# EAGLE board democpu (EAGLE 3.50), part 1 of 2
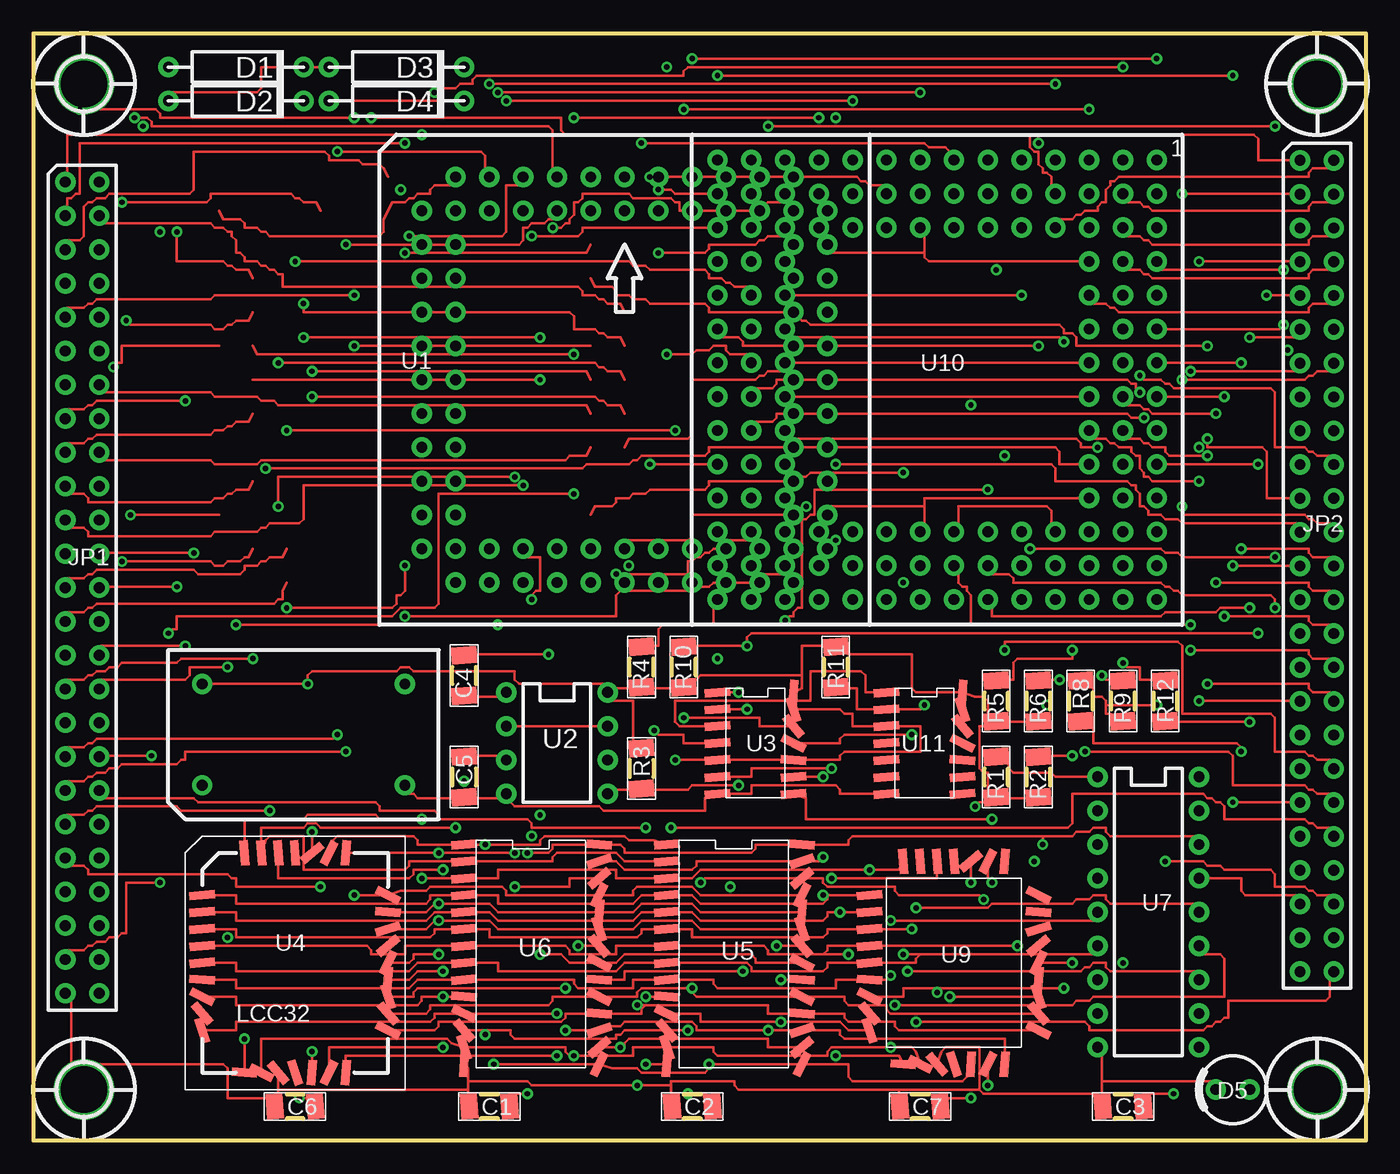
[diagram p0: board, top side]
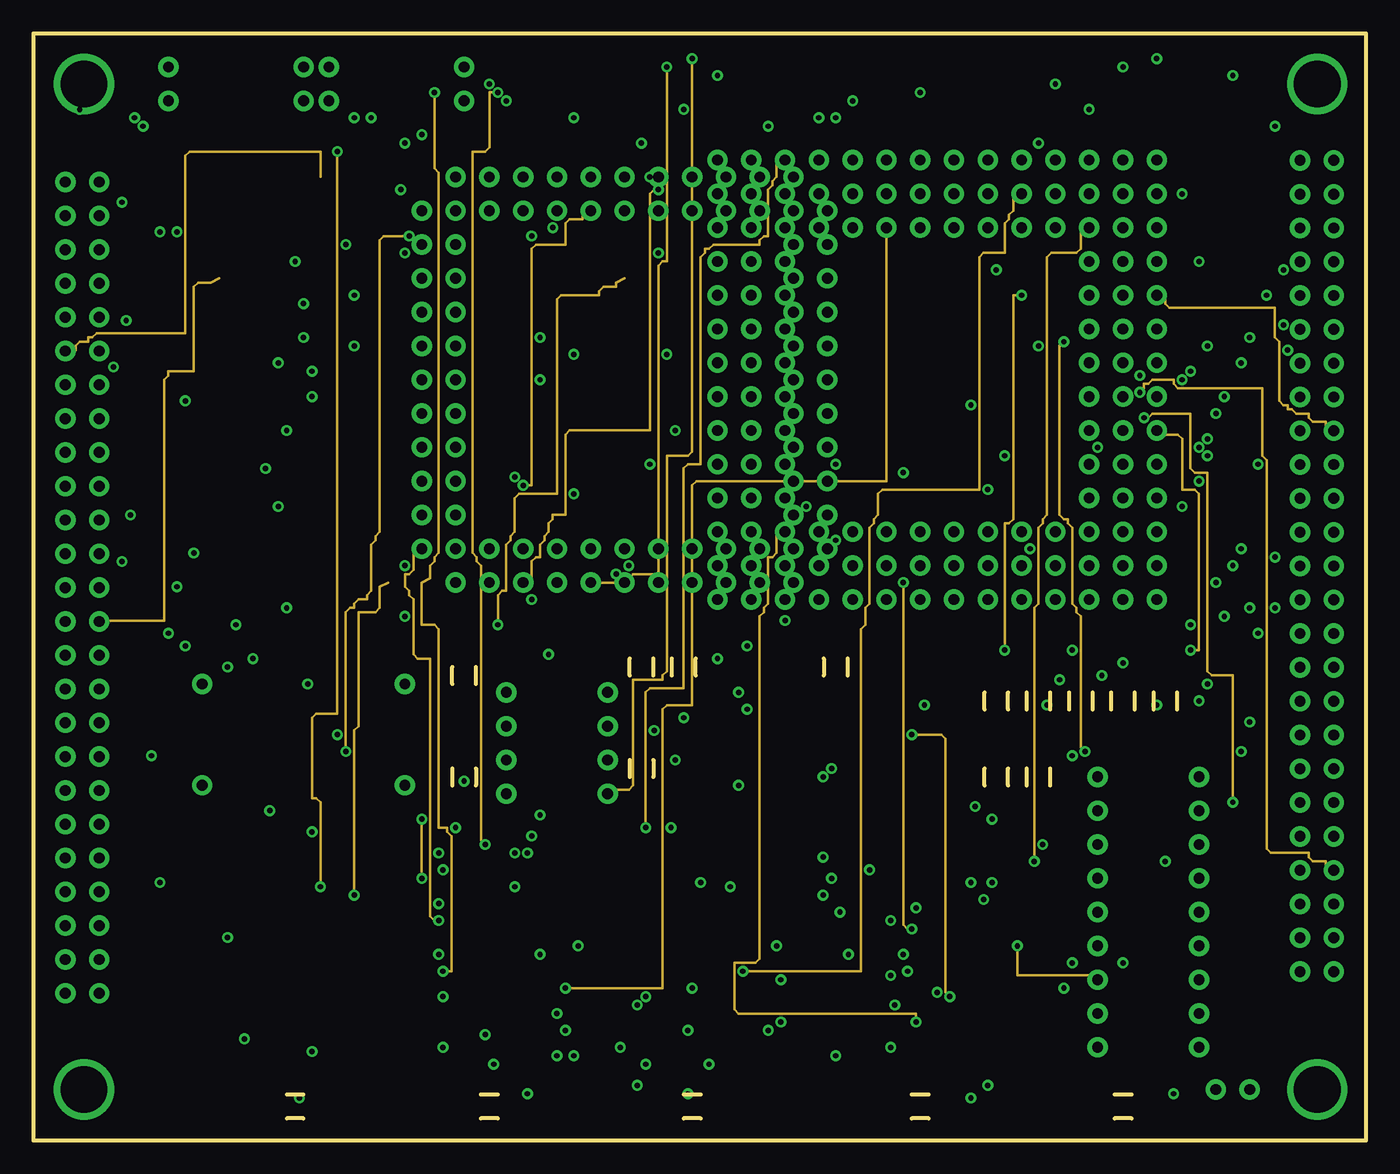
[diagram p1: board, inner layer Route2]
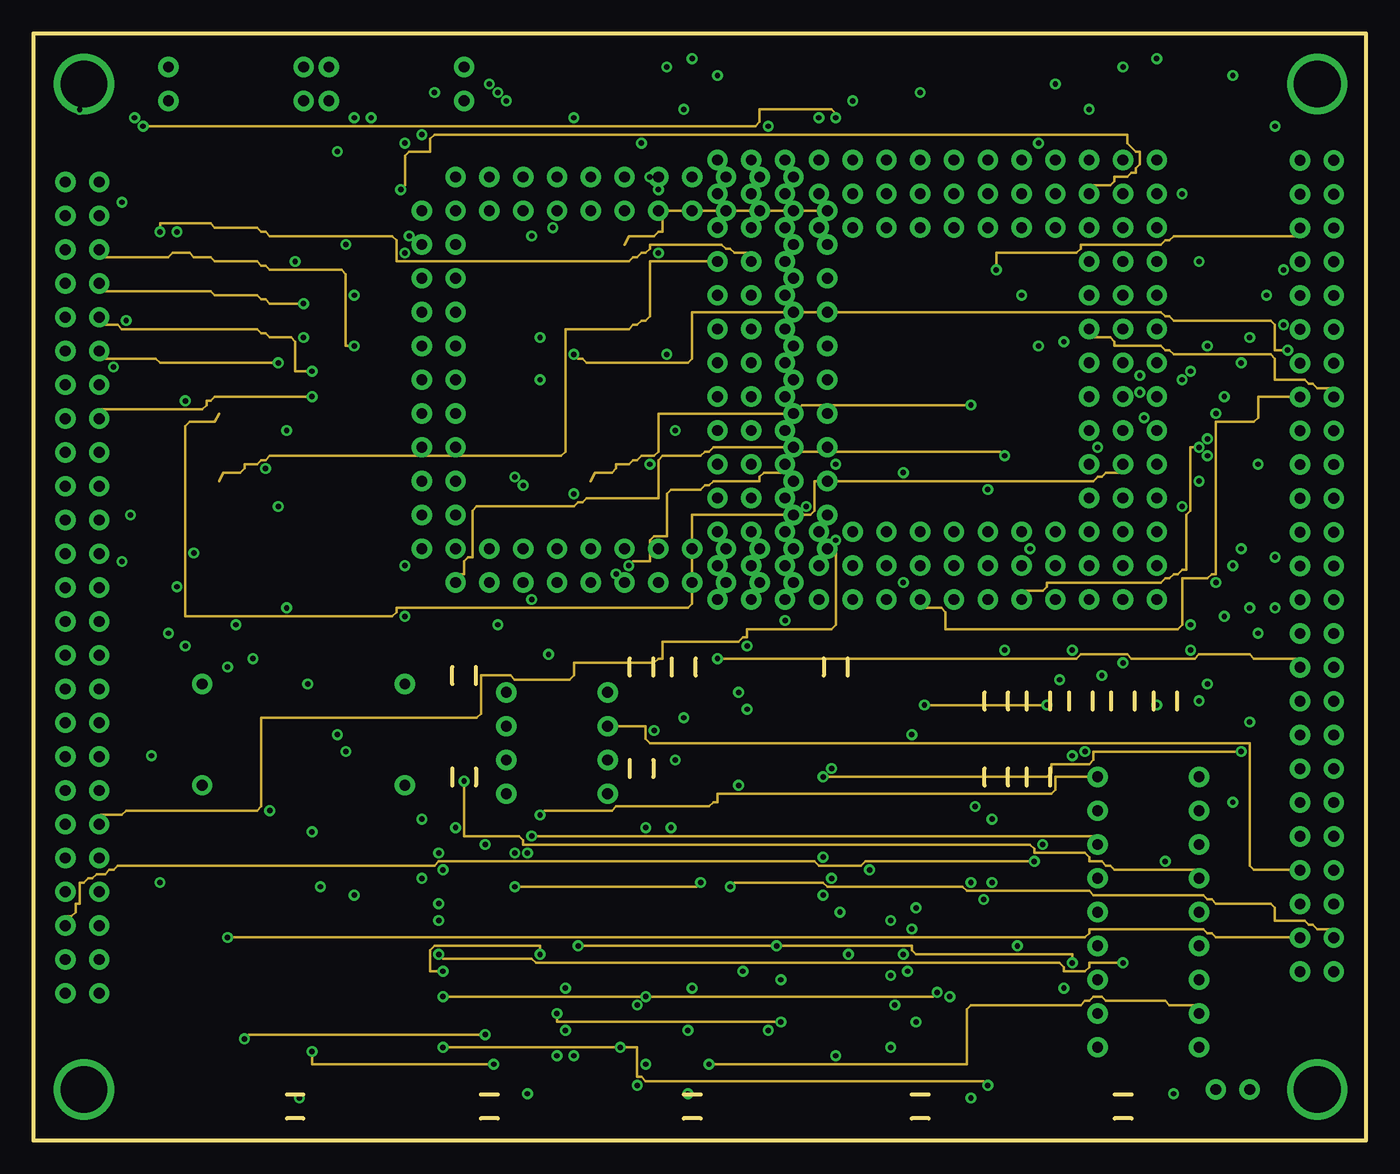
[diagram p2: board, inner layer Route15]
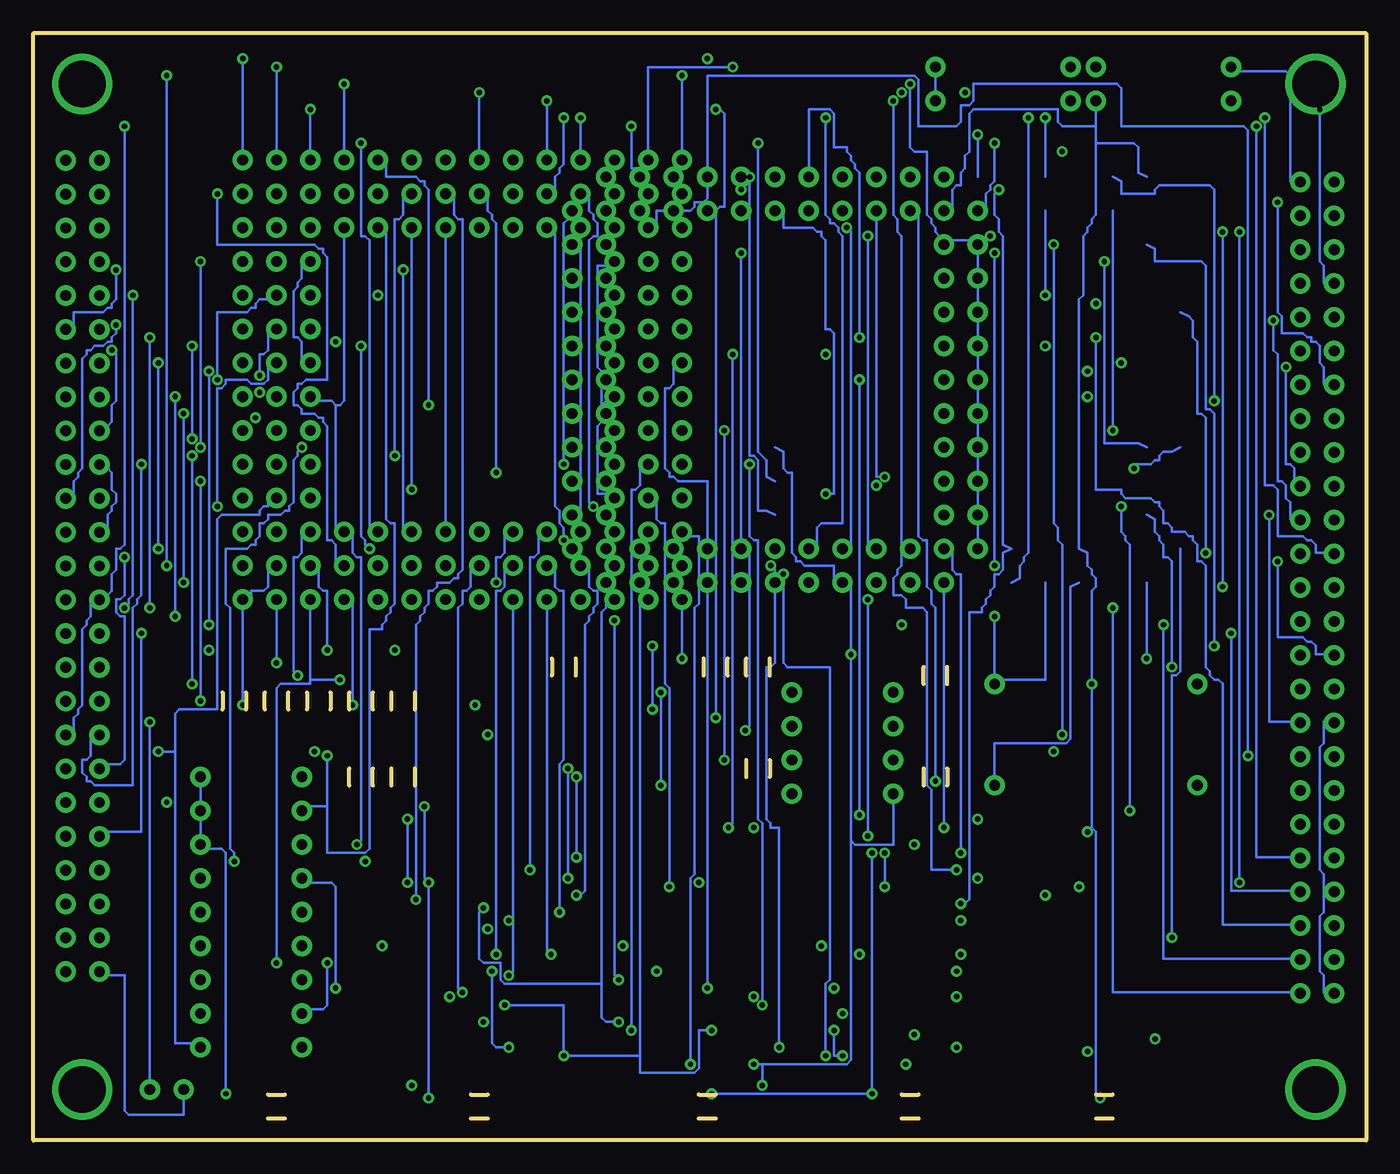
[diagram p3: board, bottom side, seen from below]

Size 100.2 x 83.19 mm. Coordinates in mm from the lower left corner, seen from the top.
Outline: 0,0 100.2,0 100.2,83.19 0,83.19 0,0
Copper layers used: Top, Route2, Route15, Bottom

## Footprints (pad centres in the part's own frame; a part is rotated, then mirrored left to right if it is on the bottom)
06 = smd 1.27 x 1.905 rotated 4.4:  1.524,0 | smd 1.27 x 1.905 rotated 4.3:  -1.524,0
4 = drill 0.813 pad 1.524 round:  0,0;  10.16,0
D = drill 0.813 pad 1.524 round:  0,0;  2.54,0
FBO3,5 = drill 3.505 pad 1.524 round:  0,0
N25X2 = drill 0.813 pad 1.524 round:  0,0;  0,2.54;  2.54,0;  2.54,2.54;  5.08,0;  5.08,2.54;  7.62,0;  7.62,2.54;  10.16,0;  10.16,2.54;  12.7,0;  15.24,0;  17.78,0;  20.32,0;  22.86,0;  25.4,0;  27.94,0;  30.48,0;  33.02,0;  35.56,0;  38.1,0;  40.64,0;  43.18,0;  45.72,0;  48.26,0;  50.8,0;  53.34,0;  55.88,0;  58.42,0;  60.96,0;  12.7,2.54;  15.24,2.54;  17.78,2.54;  20.32,2.54;  22.86,2.54;  25.4,2.54;  27.94,2.54;  30.48,2.54;  33.02,2.54;  35.56,2.54;  38.1,2.54;  40.64,2.54;  43.18,2.54;  45.72,2.54;  48.26,2.54;  50.8,2.54;  53.34,2.54;  55.88,2.54;  58.42,2.54;  60.96,2.54
CC84 = drill 0.813 pad 1.524 round:  0,-2.54;  0,-5.08;  0,-7.62;  0,-10.16;  0,-12.7;  0,-15.24;  0,-17.78;  0,-20.32;  0,-22.86;  0,-25.4;  0,-27.94;  -2.54,-30.48;  -5.08,-30.48;  -7.62,-30.48;  -10.16,-30.48;  -12.7,-30.48;  -15.24,-30.48;  -17.78,-30.48;  -20.32,-30.48;  -22.86,-30.48;  -25.4,-30.48;  -27.94,-30.48;  -30.48,-27.94;  -30.48,-25.4;  -30.48,-22.86;  -30.48,-20.32;  -30.48,-17.78;  -30.48,-15.24;  -30.48,-12.7;  -30.48,-10.16;  -30.48,-7.62;  -30.48,-5.08;  -30.48,-2.54;  -27.94,0;  -25.4,0;  -22.86,0;  -20.32,0;  -17.78,0;  -15.24,0;  -12.7,0;  -10.16,0;  -7.62,0;  -5.08,0;  -2.54,0;  -2.54,-2.54;  -2.54,-5.08;  -2.54,-7.62;  -2.54,-10.16;  -2.54,-12.7;  -2.54,-15.24;  -2.54,-17.78;  -2.54,-20.32;  -2.54,-22.86;  -2.54,-25.4;  -2.54,-27.94;  -5.08,-27.94;  -7.62,-27.94;  -10.16,-27.94;  -12.7,-27.94;  -15.24,-27.94;  -17.78,-27.94;  -20.32,-27.94;  -22.86,-27.94;  -25.4,-27.94;  -27.94,-27.94;  -27.94,-25.4;  -27.94,-22.86;  -27.94,-20.32;  -27.94,-17.78;  -27.94,-15.24;  -27.94,-12.7;  -27.94,-10.16;  -27.94,-7.62;  -27.94,-5.08;  -27.94,-2.54;  -25.4,-2.54;  -22.86,-2.54;  -20.32,-2.54;  -17.78,-2.54;  -15.24,-2.54;  -12.7,-2.54;  -10.16,-2.54;  -7.62,-2.54;  -5.08,-2.54
L8 = drill 0.813 pad 1.524 round:  0,0;  2.54,0;  5.08,0;  7.62,0;  7.62,7.62;  5.08,7.62;  2.54,7.62;  0,7.62
14 = smd 0.635 x 1.905 rotated 4.3:  0,0;  5.08,5.715 | smd 0.635 x 1.905 rotated 94.3:  0,5.715 | smd 0.635 x 1.905 rotated 4.4:  1.27,0 | smd 0.635 x 1.905 rotated 4.5:  2.54,0 | smd 0.635 x 1.905 rotated 71.8:  1.27,5.715 | smd 0.635 x 1.905 rotated 49.3:  2.54,5.715 | smd 0.635 x 1.905 rotated 4.6:  3.81,0 | smd 0.635 x 1.905 rotated 26.8:  3.81,5.715 | smd 0.635 x 1.905 rotated 4.7:  5.08,0;  6.35,0 | smd 0.635 x 1.905 rotated 5:  6.35,5.715 | smd 0.635 x 1.905 rotated 4.8:  7.62,0 | smd 0.635 x 1.905 rotated 4.9:  7.62,5.715
C32 = smd 0.635 x 1.905 rotated 4.3:  0,0 | smd 0.635 x 1.905 rotated 4.4:  -1.27,0;  3.81,-16.51 | smd 0.635 x 1.905 rotated 4.5:  -2.54,0;  3.81,0 | smd 0.635 x 1.905 rotated 4.6:  -3.81,0 | smd 0.635 x 1.905 rotated 49.5:  1.27,0 | smd 0.635 x 1.905 rotated 27:  2.54,0 | smd 0.635 x 1.905 rotated 161.8:  0,-16.51 | smd 0.635 x 1.905 rotated 139.3:  -1.27,-16.51 | smd 0.635 x 1.905 rotated 116.8:  -2.54,-16.51 | smd 0.635 x 1.905 rotated 94.3:  -3.81,-16.51 | smd 0.635 x 1.905 rotated 184.3:  1.27,-16.51 | smd 0.635 x 1.905 rotated 206.8:  2.54,-16.51 | smd 1.905 x 0.635 rotated 4.7:  -6.985,-3.175;  -6.985,-4.445 | smd 1.905 x 0.635 rotated 4.8:  -6.985,-5.715 | smd 1.905 x 0.635 rotated 4.9:  -6.985,-6.985 | smd 1.905 x 0.635 rotated 5:  -6.985,-8.255 | smd 1.905 x 0.635 rotated 4.3:  -6.985,-9.525 | smd 1.905 x 0.635 rotated 26.8:  -6.985,-10.795 | smd 1.905 x 0.635 rotated 49.3:  -6.985,-12.065 | smd 1.905 x 0.635 rotated 71.8:  -6.985,-13.335 | smd 1.905 x 0.635 rotated 206.9:  6.985,-3.175 | smd 1.905 x 0.635 rotated 184.4:  6.985,-4.445 | smd 1.905 x 0.635 rotated 161.9:  6.985,-5.715 | smd 1.905 x 0.635 rotated 139.4:  6.985,-6.985 | smd 1.905 x 0.635 rotated 116.9:  6.985,-8.255 | smd 1.905 x 0.635 rotated 94.4:  6.985,-9.525 | smd 1.905 x 0.635 rotated 71.9:  6.985,-10.795 | smd 1.905 x 0.635 rotated 49.4:  6.985,-12.065 | smd 1.905 x 0.635 rotated 26.9:  6.985,-13.335
28L = smd 0.635 x 1.905 rotated 4.3:  0,0;  11.43,0 | smd 0.635 x 1.905 rotated 4.4:  1.27,0;  10.16,10.16 | smd 0.635 x 1.905 rotated 4.5:  2.54,0 | smd 0.635 x 1.905 rotated 4.6:  3.81,0 | smd 0.635 x 1.905 rotated 4.7:  5.08,0;  6.35,0 | smd 0.635 x 1.905 rotated 4.8:  7.62,0 | smd 0.635 x 1.905 rotated 4.9:  8.89,0 | smd 0.635 x 1.905 rotated 5:  10.16,0 | smd 0.635 x 1.905 rotated 206.8:  11.43,10.16 | smd 0.635 x 1.905 rotated 184.3:  12.7,10.16 | smd 0.635 x 1.905 rotated 161.8:  13.97,10.16 | smd 0.635 x 1.905 rotated 139.3:  15.24,10.16 | smd 0.635 x 1.905 rotated 116.8:  16.51,10.16 | smd 0.635 x 1.905 rotated 94.3:  16.51,0 | smd 0.635 x 1.905 rotated 71.8:  15.24,0 | smd 0.635 x 1.905 rotated 49.3:  13.97,0 | smd 0.635 x 1.905 rotated 26.8:  12.7,0 | smd 0.635 x 1.905 rotated 26.9:  8.89,10.16 | smd 0.635 x 1.905 rotated 49.4:  7.62,10.16 | smd 0.635 x 1.905 rotated 71.9:  6.35,10.16 | smd 0.635 x 1.905 rotated 94.4:  5.08,10.16 | smd 0.635 x 1.905 rotated 116.9:  3.81,10.16 | smd 0.635 x 1.905 rotated 139.4:  2.54,10.16 | smd 0.635 x 1.905 rotated 161.9:  1.27,10.16 | smd 0.635 x 1.905 rotated 184.4:  0,10.16
L18 = drill 0.813 pad 1.524 round:  0,0;  2.54,0;  5.08,0;  7.62,0;  10.16,0;  12.7,0;  15.24,0;  17.78,0;  20.32,0;  20.32,7.62;  17.78,7.62;  15.24,7.62;  12.7,7.62;  10.16,7.62;  7.62,7.62;  5.08,7.62;  2.54,7.62;  0,7.62
Z = drill 0.813 pad 1.524 round:  0,0;  15.24,0;  15.24,7.62;  0,7.62
CC32 = smd 0.635 x 1.905 rotated 4.3:  0,0 | smd 0.635 x 1.905 rotated 4.4:  -1.27,0;  3.81,-15.24 | smd 0.635 x 1.905 rotated 4.5:  -2.54,0;  3.81,0 | smd 0.635 x 1.905 rotated 4.6:  -3.81,0 | smd 1.905 x 0.635 rotated 4.7:  -6.35,-2.54;  -6.35,-3.81 | smd 1.905 x 0.635 rotated 71.9:  6.35,-10.16 | smd 1.905 x 0.635 rotated 49.4:  6.35,-11.43 | smd 1.905 x 0.635 rotated 26.9:  6.35,-12.7 | smd 0.635 x 1.905 rotated 206.8:  2.54,-15.24 | smd 1.905 x 0.635 rotated 94.4:  6.35,-8.89 | smd 1.905 x 0.635 rotated 116.9:  6.35,-7.62 | smd 1.905 x 0.635 rotated 139.4:  6.35,-6.35 | smd 1.905 x 0.635 rotated 161.9:  6.35,-5.08 | smd 1.905 x 0.635 rotated 184.4:  6.35,-3.81 | smd 0.635 x 1.905 rotated 184.3:  1.27,-15.24 | smd 1.905 x 0.635 rotated 4.8:  -6.35,-5.08 | smd 1.905 x 0.635 rotated 4.9:  -6.35,-6.35 | smd 1.905 x 0.635 rotated 5:  -6.35,-7.62 | smd 1.905 x 0.635 rotated 4.3:  -6.35,-8.89 | smd 1.905 x 0.635 rotated 26.8:  -6.35,-10.16 | smd 1.905 x 0.635 rotated 49.3:  -6.35,-11.43 | smd 1.905 x 0.635 rotated 71.8:  -6.35,-12.7 | smd 0.635 x 1.905 rotated 94.3:  -3.81,-15.24 | smd 0.635 x 1.905 rotated 116.8:  -2.54,-15.24 | smd 0.635 x 1.905 rotated 139.3:  -1.27,-15.24 | smd 0.635 x 1.905 rotated 161.8:  0,-15.24 | smd 0.635 x 1.905 rotated 49.5:  1.27,0 | smd 0.635 x 1.905 rotated 27:  2.54,0 | smd 1.905 x 0.635 rotated 206.9:  6.35,-2.54
A132 = drill 0.813 pad 1.524 round:  0,0;  0,-2.54;  0,-5.08;  0,-7.62;  0,-10.16;  0,-12.7;  0,-15.24;  0,-17.78;  0,-20.32;  0,-22.86;  0,-25.4;  0,-27.94;  0,-30.48;  0,-33.02;  -2.54,0;  -2.54,-2.54;  -2.54,-5.08;  -2.54,-7.62;  -2.54,-10.16;  -2.54,-12.7;  -2.54,-15.24;  -2.54,-17.78;  -2.54,-20.32;  -2.54,-22.86;  -2.54,-25.4;  -2.54,-27.94;  -2.54,-30.48;  -2.54,-33.02;  -5.08,0;  -5.08,-2.54;  -5.08,-5.08;  -5.08,-7.62;  -5.08,-10.16;  -5.08,-12.7;  -5.08,-15.24;  -5.08,-17.78;  -5.08,-20.32;  -5.08,-22.86;  -5.08,-25.4;  -5.08,-27.94;  -5.08,-30.48;  -5.08,-33.02;  -7.62,0;  -7.62,-2.54;  -7.62,-5.08;  -7.62,-27.94;  -7.62,-30.48;  -7.62,-33.02;  -10.16,0;  -10.16,-2.54;  -10.16,-5.08;  -10.16,-27.94;  -10.16,-30.48;  -10.16,-33.02;  -12.7,0;  -12.7,-2.54;  -12.7,-5.08;  -12.7,-27.94;  -12.7,-30.48;  -12.7,-33.02;  -15.24,0;  -15.24,-2.54;  -15.24,-5.08;  -15.24,-27.94;  -15.24,-30.48;  -15.24,-33.02;  -17.78,0;  -17.78,-2.54;  -17.78,-5.08;  -17.78,-27.94;  -17.78,-30.48;  -17.78,-33.02;  -20.32,0;  -20.32,-2.54;  -20.32,-5.08;  -20.32,-27.94;  -20.32,-30.48;  -20.32,-33.02;  -22.86,0;  -22.86,-2.54;  -22.86,-5.08;  -22.86,-27.94;  -22.86,-30.48;  -22.86,-33.02;  -25.4,0;  -25.4,-2.54;  -25.4,-5.08;  -25.4,-27.94;  -25.4,-30.48;  -25.4,-33.02;  -27.94,0;  -27.94,-2.54;  -27.94,-5.08;  -27.94,-7.62;  -27.94,-10.16;  -27.94,-12.7;  -27.94,-15.24;  -27.94,-17.78;  -27.94,-20.32;  -27.94,-22.86;  -27.94,-25.4;  -27.94,-27.94;  -27.94,-30.48;  -27.94,-33.02;  -30.48,0;  -30.48,-2.54;  -30.48,-5.08;  -30.48,-7.62;  -30.48,-10.16;  -30.48,-12.7;  -30.48,-15.24;  -30.48,-17.78;  -30.48,-20.32;  -30.48,-22.86;  -30.48,-25.4;  -30.48,-27.94;  -30.48,-30.48;  -30.48,-33.02;  -33.02,0;  -33.02,-2.54;  -33.02,-5.08;  -33.02,-7.62;  -33.02,-10.16;  -33.02,-12.7;  -33.02,-15.24;  -33.02,-17.78;  -33.02,-20.32;  -33.02,-22.86;  -33.02,-25.4;  -33.02,-27.94;  -33.02,-30.48;  -33.02,-33.02

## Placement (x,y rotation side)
C1  [06]  34.29,2.54 180 top
C2  [06]  49.53,2.54 180 top
C3  [06]  81.92,2.54 180 top
C4  [06]  32.38,34.92 90 top
C5  [06]  32.38,27.3 270 top
C6  [06]  19.68,2.54 180 top
C7  [06]  66.67,2.54 180 top
D1  [4]  20.32,80.65 180 top
D2  [4]  20.32,78.1 180 top
D3  [4]  32.38,80.65 180 top
D4  [4]  32.38,78.1 180 top
D5  [D]  88.9,3.81 0 top
E$38  [FBO3,5]  3.81,79.38 90 top
E$39  [FBO3,5]  3.81,3.81 0 top
E$40  [FBO3,5]  96.52,3.81 0 top
E$41  [FBO3,5]  96.52,79.38 180 top
JP1  [N25X2]  2.41,72.01 270 top
JP2  [N25X2]  95.22,73.63 270 top
R1  [06]  72.39,27.3 90 top
R2  [06]  75.56,27.3 90 top
R3  [06]  45.72,27.94 270 top
R4  [06]  45.72,35.56 90 top
R5  [06]  72.39,33.02 90 top
R6  [06]  75.56,33.02 90 top
R8  [06]  78.74,33.02 270 top
R9  [06]  81.92,33.02 90 top
R10  [06]  48.9,35.56 90 top
R11  [06]  60.33,35.56 270 top
R12  [06]  85.09,33.02 270 top
U1  [CC84]  29.21,72.39 90 top
U2  [L8]  35.56,33.66 270 top
U3  [14]  51.44,33.66 270 top
U4  [C32]  19.68,21.59 0 top
U5  [28L]  47.62,22.23 270 top
U6  [28L]  32.38,22.23 270 top
U7  [L18]  80.01,27.3 270 top
U8  [Z]  12.7,26.67 0 top
U9  [CC32]  69.22,20.96 0 top
U10  [A132]  84.45,73.66 0 top
U11  [14]  64.14,33.66 270 top

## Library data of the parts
C1-C7 R1-R6 R8-R12 U3-U6 U9 U11 = SMDPACK
D1-D5 = SEMICON
E$38-E$41 U1 U2 U7 U8 U10 = PACKAGES
JP1 JP2 = CONNEC

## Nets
A0-1: JP2. U10.
A1-1: JP2. U10.
A2-1: JP2. U10.
A3-1: JP2. U10.
A4-1: JP2. U10.
A5-1: JP2. U10.
A6-1: JP2. U10.
A7-1: JP2. U10.
A8-1: JP2. U10.
A9-1: JP2. U10.
A10-1: JP2. U10.
A11-1: JP2. U10.
A12-1: JP2. U10.
A13-1: JP2. U10.
A14-1: JP2. U10.
A15-1: JP2. U10.
ALE-1: JP2. U10.
ALEM-1: U1. U7. U10.
AM0-1: U4. U5. U6. U7. U9. U10.
AM1-1: U4. U5. U6. U7. U9. U10.
AM2-1: U4. U5. U6. U7. U9. U10.
AM3-1: U4. U5. U6. U7. U9. U10.
AM4-1: U4. U5. U6. U9. U10.
AM5-1: U4. U5. U6. U9. U10.
AM6-1: U4. U5. U6. U9. U10.
AM7-1: U4. U5. U6. U9. U10.
B0-1: JP1. U1.
B1-1: JP1. U1.
BC1-1: JP1. U1.
BDIR-1: JP1. U1.
CCLK-1: JP2. U10.
CLK-1: U1. U8. U10.
CS0-1: JP1. U10.
CS1-1: JP1. U10.
CS2-1: JP1. U10.
CS3-1: JP1. U10.
CS4-1: U4. U10.
CS5-1: U5. U10.
CS6-1: U6. U10.
CS7-1: R2. U7. U10.
CS8-1: U3. U10.
CS9-1: U3. U10.
D1-1: JP2. U10.
D2-1: JP2. U10.
D3-1: JP2. U10.
D4-1: JP2. U10.
D5-1: JP2. U10.
D6-1: JP2. U10.
D7-1: JP2. U10.
DIN-1: JP2. U10.
DM0-1: U4. U5. U6. U7. U9. U10.
DM1-1: U4. U5. U6. U7. U9. U10.
DM2-1: U4. U5. U6. U7. U9. U10.
DM3-1: U4. U5. U6. U7. U9. U10.
DM4-1: U4. U5. U6. U9. U10.
DM5-1: U4. U5. U6. U9. U10.
DM6-1: U4. U5. U6. U9. U10.
DM7-1: U4. U5. U6. U9. U10.
DP0-1: JP2. U10.
DP1-1: JP2. U10.
DP2-1: JP2. U10.
DP3-1: JP2. U10.
DP4-1: JP2. U10.
DP5-1: JP2. U10.
DP6-1: JP2. U10.
DP7-1: JP2. U10.
EP0-1: U1. U10.
EP1-1: U1. U10.
GND: C1. C2. C3. C4. C5. C6. C7. D5. JP1. JP2. U1. U2. U3. U4. U5. U6. U7. U8. U9. U10. U11.
HDC-1: R12. U10.
LDC-1: R11. U10. U11.
N00044: R5. U10.
N00107: D1. D2. D3.
N00117: C5. U2.
N00118: C4. U2.
N00119: U3. U9.
N00121: U3. U9.
N00124: U3. U9.
N00135: U3. U11.
N00157: D5. R12.
P00-1: U1. U10.
P01-1: U1. U10.
P02-1: U1. U10.
P03-1: U1. U10.
P04-1: U1. U10.
P05-1: U1. U10.
P06-1: U1. U10.
P07-1: U1. U10.
P10-1: JP1. U1.
P11-1: JP1. U1.
P12-1: JP1. U1.
P13-1: JP1. U1.
P14-1: JP2. U1.
P15-1: JP1. U1.
P16-1: JP1. U1.
P20-1: U1. U4. U5. U6. U10.
P21-1: U1. U4. U5. U6. U10.
P22-1: U1. U4. U5. U6. U10.
P23-1: U1. U4. U5. U6. U10.
P24-1: U1. U4. U5. U6. U10.
P25-1: U1. U4. U5. U6. U10.
P26-1: U1. U4. U5. U6. U10.
P27-1: U1. U4. U10.
P40-1: JP1. U1.
P41-1: JP1. U1.
P42-1: JP1. U1.
P43-1: JP1. U1.
P44-1: JP1. U1.
P45-1: JP1. U1.
P46-1: JP1. U1.
P47-1: JP1. U1.
P50-1: JP1. U1.
P51-1: JP1. U1.
P52-1: JP1. U1.
P53-1: JP1. U1.
P54-1: JP1. U1.
P55-1: JP1. U1.
P56-1: JP1. U1.
P57-1: JP1. U1.
P66-1: JP1. U1.
P67-1: JP1. U1.
P70-1: JP1. U1.
P71-1: JP1. U1.
P72-1: JP1. U1.
P73-1: JP1. U1.
P74-1: JP1. U1.
P75-1: JP1. U1.
P80-1: JP1. U1.
P81-1: JP1. U1.
P82-1: JP1. U1.
P83-1: JP1. U1.
PDWN-1: R3. U2. U3. U10.
PSEN-1: JP2. U10.
PSENM-1: U1. U10.
RD-1: JP2. U10.
RDM-1: U5. U6. U7. U9.
RDP-1: U1. U10.
RDR-1: JP1. U10.
RDRM-1: R6. U4. U10.
RES-1: U1. U3. U11.
RLCA-1: JP2. R4. U10.
RSI-1: JP2. R10. U3.
RSO-1: JP2. U1. U7.
RX0-1: JP2. U1.
RX1-1: JP2. U1.
S$1: D3. D4.
S$2: U1.
S$3: R8. R9. U10.
SENS-1: JP2. U2.
STD-1: R1. U1. U7.
T0-1: JP1. U1.
T2-1: JP1. U1.
TX1-1: JP2. U1.
VB: C1. C2. C3. JP2. U5. U6. U7. U10.
VCC: C6. C7. D2. R1. R2. R3. R4. R5. R6. R10. R11. U1. U2. U3. U4. U8. U9. U11.
VM: D1. JP1.
WR-1: JP2. U10.
WRM-1: R8. U3. U5. U6. U7. U10.
WRP-1: U1. U10.
WRR-1: JP1. U10.
WRRM-1: R9. U10.

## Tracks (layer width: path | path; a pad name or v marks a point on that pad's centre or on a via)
A0-1
  Top 0.203: 97.77,71.09 97.47,70.49 96.2,70.49 95.89,70.17 95.89,69.85 84.14,69.85 83.82,70.17 83.5,70.17 83.19,70.49 82.23,70.49 81.92,71.12
A1-1
  Top 0.203: 97.77,68.56 97.47,67.94 96.2,67.94 95.89,67.63 95.89,67.31 84.14,67.31 83.82,67.63 83.5,67.63 83.19,67.94 82.23,67.94 81.92,68.58
A2-1
  Top 0.203: 97.77,66.02 97.47,65.41 96.2,65.41 95.89,65.09 95.89,64.77 84.14,64.77 83.82,65.09 83.5,65.09 83.19,65.41 82.23,65.41 81.92,66.04
A3-1
  Top 0.203: 97.77,63.48 97.47,62.87 96.2,62.87 95.89,62.55 95.89,62.23 81.6,62.23 81.28,62.55 80.96,62.55 80.64,62.87 79.69,62.87 79.38,63.5
A4-1  (via drill 0.41 pad 0.61)
  Top 0.203: v93.98,65.41 84.77,65.41 84.45,66.04
  Bottom 0.203: v93.98,65.41 93.98,63.18 94.3,62.87 94.3,62.55 94.61,62.55 94.93,62.23 97.16,62.23 97.16,61.28 97.77,60.94
A5-1  (via drill 0.41 pad 0.61)
  Top 0.203: v86.36,57.15 95.57,57.15 95.89,57.47 96.2,57.47 96.52,57.79 97.47,57.79 97.77,58.4
  Bottom 0.203: v86.36,57.15 86.36,62.23 84.14,62.23 83.82,62.55 83.5,62.55 83.5,62.87 83.19,63.18 82.55,63.18 81.92,63.5
A6-1
  Route15 0.203: 79.38,60.96 79.69,60.33 80.96,60.33 81.28,60.01 81.28,59.69 84.77,59.69 85.09,59.37 85.41,59.37 85.72,59.05 93.03,59.05 93.34,58.74 93.34,57.15 95.57,57.15 95.89,56.83 96.2,56.83 96.52,56.52 97.47,56.52 97.77,55.85
A7-1
  Route2 0.203: 84.45,63.5 85.09,63.18 85.09,62.87 85.41,62.55 93.34,62.55 93.34,60.33 93.66,60.01 93.66,55.56 93.98,55.24 94.3,55.24 94.3,54.93 94.61,54.93 94.93,54.61 95.89,54.61 95.89,54.29 96.2,53.98 97.16,53.98 97.16,53.66 97.77,53.31
A8-1  (via drill 0.41 pad 0.61)
  Top 0.203: v83.19,57.47 83.5,57.15 84.77,57.15 85.09,56.83 85.41,56.83 85.72,56.52 93.03,56.52 93.34,56.2 93.34,52.07 95.57,52.07 95.89,51.75 96.2,51.75 96.52,51.44 97.47,51.44 97.77,50.77
  Bottom 0.203: v83.19,57.47 83.19,59.05 82.87,59.05 82.55,59.37 82.55,60.64 81.92,60.96
A9-1  (via drill 0.41 pad 0.61)
  Top 0.203: v93.98,61.28 93.66,60.96 84.45,60.96
  Bottom 0.203: v93.98,61.28 93.98,60.64 94.3,60.33 94.3,60.01 94.61,60.01 94.93,59.69 95.57,59.69 95.89,59.37 96.2,59.37 96.2,59.05 96.52,58.74 96.52,50.48 96.84,50.16 96.84,49.85 97.16,49.53 97.16,48.58 97.77,48.23
A10-1  (via drill 0.41 pad 0.61)
  Top 0.203: v86.36,47.62 86.36,46.99 95.57,46.99 95.89,46.67 96.2,46.67 96.52,46.35 97.47,46.35 97.77,45.7
  Bottom 0.203: v86.36,47.62 86.36,56.52 86.04,56.52 85.72,56.83 85.72,57.15 84.14,57.15 83.82,56.83 82.87,56.83 82.55,57.15 82.55,58.1 81.92,58.42
A11-1  (via drill 0.41 pad 0.61)
  Top 0.203: v90.81,44.45 95.89,44.45 95.89,44.13 96.2,43.81 97.47,43.81 97.77,43.16 | v90.81,58.42 84.45,58.42
  Bottom 0.203: v90.81,44.45 v90.81,58.42
A12-1  (via drill 0.41 pad 0.61)
  Top 0.203: v88.9,41.91 95.89,41.91 95.89,41.59 96.2,41.27 97.47,41.27 97.77,40.62 | v88.9,54.61 84.14,54.61 83.82,54.93 83.5,54.93 83.19,55.24 82.23,55.24 81.92,55.88
  Bottom 0.203: v88.9,41.91 v88.9,54.61
A13-1  (via drill 0.41 pad 0.61)
  Top 0.203: v89.53,39.37 95.89,39.37 95.89,39.05 96.2,38.73 97.47,38.73 97.77,38.08 | v89.53,55.88 84.45,55.88
  Bottom 0.203: v89.53,39.37 v89.53,55.88
A14-1  (via drill 0.41 pad 0.61)
  Top 0.203: v87,36.83 95.89,36.83 95.89,36.51 96.2,36.2 97.47,36.2 97.77,35.53
  Route2 0.203: v87,36.83 87.63,36.83 87.63,48.58 87.31,48.9 86.36,48.9 86.36,52.7 86.04,53.02 85.09,53.02 84.45,53.34
A15-1  (via drill 0.41 pad 0.61)
  Top 0.203: v88.27,34.29 95.89,34.29 95.89,33.97 96.2,33.66 97.47,33.66 97.77,33 | v88.27,51.44 85.41,51.44 85.09,51.75 85.09,52.07 84.14,52.07 83.82,52.39 83.5,52.39 83.19,52.7 82.23,52.7 81.92,53.34
  Bottom 0.203: v88.27,34.29 v88.27,51.44
ALE-1  (via drill 0.41 pad 0.61)
  Top 0.203: v87.63,33.02 94.61,33.02 95.22,33 | v87.63,49.53 84.14,49.53 83.82,49.85 83.5,49.85 83.5,50.16 83.19,50.48 83.19,51.44 82.87,51.44 82.55,51.75 82.55,52.07 81.6,52.07 81.28,52.39 80.96,52.39 80.64,52.7 79.69,52.7 79.38,53.34
  Bottom 0.203: v87.63,33.02 v87.63,49.53
ALEM-1  (via drill 0.41 pad 0.61)
  Top 0.203: v37.47,67.94 40.96,67.94 41.27,68.26 41.27,68.58 51.44,68.58 | v37.47,40.64 37.47,40.96 37.78,41.27 38.1,41.27 38.1,43.81 37.15,43.81 36.83,44.45
  Route15 0.203: v37.47,22.86 79.69,22.86 80.01,22.23
  Bottom 0.203: v37.47,67.94 37.47,44.77 36.83,44.45 | v37.47,22.86 v37.47,40.64
AM0-1  (via drill 0.41 pad 0.61)
  Top 0.203: 12.7,10.79 15.24,10.79 15.24,10.16 28.89,10.16 29.21,10.48 29.21,10.79 v30.8,10.79 32.38,10.79 | v46.04,10.79 47.62,10.79 | 67.94,11.43 v77.47,11.43 | 67.94,11.43 65.41,11.43 65.41,10.79 62.87,10.79 | v67.94,11.11 67.94,11.43
  Route15 0.203: v30.8,10.79 v46.04,10.79 67.63,10.79 v67.94,11.11
  Bottom 0.203: v77.47,11.43 77.47,19.05 77.79,19.37 79.38,19.37 80.01,19.69 | v67.94,11.11 68.26,11.43 68.26,40.01 67.94,40.32 67.94,41.27 67.63,41.27 67.31,41.59 67.31,42.86 66.67,43.18
AM1-1  (via drill 0.41 pad 0.61)
  Top 0.203: 12.7,12.07 15.24,12.07 15.24,11.43 28.26,11.43 28.89,12.07 32.38,12.07 40.64,12.07 40.64,11.75 40.96,11.43 45.09,11.43 45.09,12.07 47.62,12.07 51.12,12.07 51.12,11.75 51.44,11.43 60.33,11.43 60.33,12.07 62.87,12.07 64.14,12.07 v64.45,12.38 | v64.45,16.51 79.69,16.51 80.01,17.14
  Bottom 0.203: 64.14,16.51 64.14,12.7 v64.45,12.38 | 64.14,16.51 64.14,40.64 | 64.14,16.51 v64.45,16.51
AM2-1  (via drill 0.41 pad 0.61)
  Top 0.203: 12.7,13.34 15.24,13.34 15.24,12.7 28.26,12.7 28.89,13.34 32.38,13.34 34.92,13.34 34.92,12.7 43.81,12.7 44.45,13.34 47.62,13.34 53.66,13.34 53.98,13.02 53.98,12.7 59.37,12.7 59.69,13.02 59.69,13.34 62.87,13.34 66.36,13.34 66.36,13.65 66.67,13.97 | 66.67,13.97 79.69,13.97 80.01,14.61 | 66.67,13.97 v65.41,13.97
  Bottom 0.203: v65.41,13.97 65.41,41.27 65.09,41.27 64.77,41.59 64.77,42.86 64.14,43.18
AM3-1  (via drill 0.41 pad 0.61)
  Top 0.203: 12.7,14.61 25.08,14.61 25.4,14.29 25.4,13.97 27.94,13.97 27.94,14.61 32.38,14.61 40.01,14.61 40.32,14.29 40.32,13.97 43.81,13.97 43.81,14.61 47.62,14.61 54.93,14.61 55.24,14.29 55.24,13.97 59.37,13.97 | 59.37,13.97 59.69,14.29 59.69,14.61 62.87,14.61 v73.98,14.61 | 59.37,13.97 v61.28,13.97
  Route2 0.203: v73.98,14.61 73.98,12.38 79.38,12.38 80.01,12.07
  Bottom 0.203: v61.28,13.97 61.59,14.29 61.59,40.64
AM4-1  (via drill 0.41 pad 0.61)
  Top 0.203: 12.7,15.88 15.24,15.88 15.24,15.24 29.84,15.24 30.16,15.56 30.16,15.88 32.38,15.88 34.29,15.88 34.29,15.24 45.4,15.24 45.72,15.56 45.72,15.88 47.62,15.88 49.53,15.88 49.53,15.24 59.37,15.24 59.69,15.56 59.69,15.88 62.87,15.88 v66.04,15.88
  Route2 0.203: v65.41,41.91 65.41,16.19 65.72,15.88 v66.04,15.88
  Bottom 0.203: v65.41,41.91 65.41,43.81 65.09,43.81 64.77,44.13 64.77,45.4 64.14,45.72
AM5-1  (via drill 0.41 pad 0.61)
  Top 0.203: 12.7,17.14 15.24,17.14 15.24,16.51 29.53,16.51 30.16,17.14 32.38,17.14 34.29,17.14 34.92,16.51 45.09,16.51 45.72,17.14 47.62,17.14 49.53,17.14 50.16,16.51 59.37,16.51 59.69,16.83 59.69,17.14 v60.64,17.14 62.87,17.14
  Bottom 0.203: v60.64,17.14 60.64,28.26 60.33,28.57 60.33,41.27 60.64,41.27 60.96,41.59 60.96,42.86 61.59,43.18
AM6-1  (via drill 0.41 pad 0.61)
  Top 0.203: 12.7,18.41 15.24,18.41 15.24,17.78 29.53,17.78 29.84,18.1 29.84,18.41 32.38,18.41 34.92,18.41 34.92,17.78 45.09,17.78 45.72,18.41 47.62,18.41 49.53,18.41 50.16,17.78 59.37,17.78 59.69,18.1 59.69,18.41 | 59.69,18.41 62.87,18.41 | 59.69,18.41 v59.37,18.41
  Bottom 0.203: v59.37,18.41 59.05,18.41 58.74,18.73 58.74,38.73 58.42,39.05 58.42,39.37 58.1,39.69 58.1,40.01 57.78,40.32 57.78,41.27 58.1,41.27 58.42,41.59 58.42,42.86 59.05,43.18
AM7-1  (via drill 0.41 pad 0.61)
  Top 0.203: v29.21,24.13 26.04,24.13 25.72,24.45 20.64,24.45 20.32,24.13 15.88,24.13 15.88,21.59 | v29.21,19.69 32.38,19.69 34.92,19.69 34.92,20.32 43.81,20.32 43.81,19.69 47.62,19.69 49.53,19.69 50.16,20.32 v62.87,20.32 65.09,20.32 65.41,20.96
  Route2 0.203: v29.21,24.13 v29.21,19.69
  Bottom 0.203: v62.87,20.32 62.87,43.81 62.55,43.81 62.23,44.13 62.23,45.4 61.59,45.72
B0-1  (via drill 0.41 pad 0.61)
  Top 0.203: v10.16,38.1 10.48,38.42 10.79,38.42 10.79,39.37 26.99,39.37 27.62,40.01 30.16,40.01 30.48,40.32 30.48,48.58 v40.64,48.58
  Bottom 0.203: v10.16,38.1 10.16,18.73 5.71,18.73 4.95,18.67 | v40.64,48.58 40.01,48.58 40.01,60.64 40.32,60.96 40.64,60.96 40.64,67.63 40.96,67.94 40.96,68.26 41.27,68.26 41.59,68.58 43.81,68.58 43.81,69.53 44.45,69.85
B1-1  (via drill 0.41 pad 0.61)
  Top 0.203: v20.32,60.33 v38.1,60.33
  Bottom 0.203: v20.32,60.33 20.32,48.9 18.41,48.9 18.41,48.58 18.1,48.26 16.19,48.26 15.88,47.94 15.56,47.94 15.56,47.62 15.24,47.31 15.24,46.35 14.92,46.35 14.61,46.04 14.61,45.72 13.65,45.72 13.34,45.4 13.02,45.4 13.02,45.09 12.7,44.77 12.7,43.5 12.38,43.5 12.06,43.18 12.06,35.56 11.75,35.24 11.75,34.92 11.43,34.61 11.11,34.61 10.79,34.29 10.79,16.19 5.71,16.19 4.95,16.13 | v38.1,60.33 38.1,72.71 38.42,73.03 38.42,73.34 38.73,73.66 38.73,73.98 39.05,74.29 39.05,74.61 40.01,74.61 40.01,77.15 40.32,77.47 41.91,77.47 41.91,72.39
BC1-1  (via drill 0.41 pad 0.61)
  Top 0.203: v19.05,40.01 26.99,40.01 27.3,40.32 27.3,40.96 27.62,40.96 27.94,41.27 v27.94,43.18 | v27.94,66.67 41.59,66.67 41.91,67.31
  Bottom 0.203: v19.05,40.01 19.05,11.11 5.71,11.11 JP1. | v27.94,43.18 v27.94,66.67
BDIR-1  (via drill 0.41 pad 0.61)
  Top 0.203: v15.24,38.73 v34.92,38.73
  Route2 0.203: v34.92,38.73 34.92,40.96 35.24,41.27 35.56,41.27 35.56,44.77 35.88,45.09 35.88,45.4 36.2,45.72 36.2,48.26 36.51,48.58 39.37,48.58 39.37,63.18 39.69,63.5 42.55,63.5 42.55,63.82 42.86,64.13 43.81,64.13 43.81,64.45 44.45,64.77
  Bottom 0.203: v15.24,38.73 15.24,13.65 5.71,13.65 4.95,13.59
CCLK-1  (via drill 0.41 pad 0.61)
  Top 0.203: v51.44,80.01 v90.17,80.01 | v90.17,43.18 94.61,43.18 95.22,43.16
  Bottom 0.203: v90.17,80.01 v90.17,43.18 | 51.44,73.66 v51.44,80.01
CLK-1  (via drill 0.41 pad 0.61)
  Top 0.203: v27.94,39.37 43.81,39.37 43.81,40.96 44.13,41.27 49.53,41.27 49.85,41.59 50.8,41.59 51.12,41.91 54.61,41.91 54.61,42.23 54.93,42.55 56.2,42.55 56.52,43.18
  Bottom 0.203: 24.13,41.91 24.13,34.61 27.3,34.61 27.94,34.29 v27.94,39.37
CS0-1  (via drill 0.41 pad 0.61)
  Top 0.203: v8.89,28.89 5.71,28.89 4.95,28.83
  Bottom 0.203: v8.89,28.89 8.89,75.88 9.21,76.2 18.41,76.2 18.41,79.06 18.73,79.38 29.53,79.38 29.53,78.1 29.84,77.79 30.48,77.79 30.48,76.52 30.8,76.2 33.66,76.2 33.66,79.69 33.97,80.01 49.53,80.01 49.53,70.8 49.85,70.49 50.48,70.49 50.48,70.17 50.8,69.85 53.34,69.85 53.34,68.9 53.98,68.58
CS1-1  (via drill 0.41 pad 0.61)
  Top 0.203: v46.04,23.5 37.47,23.5 37.47,23.81 37.15,24.13 30.48,24.13 30.48,24.45 30.16,24.77 26.04,24.77 26.04,25.08 25.72,25.4 12.38,25.4 12.06,25.72 5.4,25.72 4.95,26.29
  Route2 0.203: v46.04,23.5 46.04,33.66 46.35,33.97 48.9,33.97 48.9,50.48 49.21,50.8 50.16,50.8 50.16,66.36 50.48,66.67 50.48,66.99 50.8,66.99 51.12,67.31 54.61,67.31 54.61,67.63 54.93,67.94 55.24,67.94 55.24,71.44 55.56,71.75 55.56,72.07 55.88,72.39 55.88,73.34 56.52,73.66
CS2-1  (via drill 0.41 pad 0.61)
  Route15 0.203: v60.33,45.09 60.33,38.73 60.01,38.42 53.66,38.42 53.66,37.78 53.34,37.78 53.02,37.47 47.31,37.47 47.31,36.2 46.99,36.2 46.67,35.88 40.64,35.88 40.64,34.92 40.32,34.61 36.2,34.61 35.88,34.92 33.66,34.92 33.66,32.07 33.34,31.75 17.14,31.75 17.14,25.08 16.83,24.77 6.99,24.77 6.67,24.45 5.08,24.45 4.95,23.75
  Bottom 0.203: v60.33,45.09 60.33,46.04 60.64,46.35 60.64,47.31 60.96,47.62 60.96,68.26 61.59,68.58
CS3-1  (via drill 0.41 pad 0.61)
  Route15 0.203: v8.26,76.2 54.29,76.2 54.61,76.52 54.61,77.47 60.01,77.47 60.33,77.15 v60.33,76.84
  Bottom 0.203: v8.26,76.2 8.26,21.27 5.71,21.27 4.95,21.21 | v60.33,76.84 60.33,73.34 60.64,73.03 60.64,72.71 60.96,72.39 60.96,71.44 61.59,71.12
CS4-1  (via drill 0.41 pad 0.61)
  Top 0.203: v40.01,11.43 28.89,11.43 28.57,11.11 28.57,10.79 26.67,10.79
  Route2 0.203: v40.01,11.43 47.31,11.43 47.31,32.39 47.62,32.7 49.53,32.7 49.53,49.21 49.85,49.53 64.14,49.53 64.14,68.58
CS5-1  (via drill 0.41 pad 0.61)
  Top 0.203: v56.52,39.05 56.83,39.37 57.15,39.37 57.15,39.69 57.47,40.01 57.78,40.01 57.78,46.67 58.1,46.67 58.42,46.99 58.74,46.99 58.74,48.9 v71.75,48.9 | 57.78,12.07 v56.2,12.07
  Bottom 0.203: v56.2,12.07 56.52,12.38 v56.52,39.05 | v71.75,48.9 71.75,68.58
CS6-1  (via drill 0.41 pad 0.61)
  Top 0.203: v53.34,12.7 44.45,12.7 44.45,12.07 42.55,12.07
  Route2 0.203: v53.34,12.7 62.23,12.7 62.23,38.42 62.55,38.73 62.55,40.01 62.87,40.32 62.87,46.04 63.18,46.35 63.18,46.67 63.5,46.99 63.5,48.58 63.82,48.9 71.12,48.9 71.12,66.36 71.44,66.67 73.03,66.67 73.03,68.9 73.34,69.22 73.34,69.53 73.66,69.85 73.66,70.8 74.3,71.12
CS7-1  (via drill 0.41 pad 0.61)
  Top 0.203: v78.11,28.89 76.52,28.89 75.56,28.83
  Bottom 0.203: 78.11,25.08 79.38,25.08 80.01,24.77 | 78.11,25.08 v78.11,28.89 | 78.11,25.08 78.11,21.59 75.25,21.59 74.93,21.91 74.93,38.42 73.98,38.42 73.98,38.73 73.66,39.05 73.66,39.37 73.34,39.69 73.34,40.01 73.03,40.32 73.03,46.35 73.34,46.35 73.66,46.67 73.66,68.26 74.3,68.58
CS8-1  (via drill 0.41 pad 0.61)
  Top 0.203: v48.9,31.75 54.61,31.75 54.61,31.12 57.15,31.12 | v48.9,77.47 v79.38,77.47
  Bottom 0.203: v48.9,31.75 48.9,69.85 48.58,70.17 48.26,70.17 48.26,77.15 48.58,77.47 v48.9,77.47 | v79.38,77.47 79.38,73.66
CS9-1  (via drill 0.41 pad 0.61)
  Top 0.203: v46.67,30.8 46.99,30.48 48.9,30.48 48.9,29.84 51.44,29.84 | v46.99,66.67 50.48,66.67 50.8,66.99 50.8,67.31 54.29,67.31 54.61,67.63 54.93,67.63 55.24,67.94 56.2,67.94 56.52,68.58
  Bottom 0.203: v46.67,30.8 46.35,31.12 46.35,44.77 46.67,45.09 46.99,45.09 v46.99,66.67
D1-1  (via drill 0.41 pad 0.61)
  Top 0.203: v73.03,36.83 73.03,37.47 86.04,37.47 86.36,37.15 86.36,32.07 93.03,32.07 93.34,31.75 93.34,29.21 95.57,29.21 95.89,28.89 96.2,28.89 96.52,28.57 97.47,28.57 97.77,27.91 | v74.3,63.5 56.52,63.5
  Route2 0.203: v74.3,63.5 73.66,63.5 73.66,46.67 73.34,46.35 73.03,46.35 v73.03,36.83
D2-1  (via drill 0.41 pad 0.61)
  Top 0.203: v77.47,60.01 77.15,60.33 56.83,60.33 56.52,60.96 | v79.06,29.21 89.85,29.21 90.17,28.89 90.17,26.67 95.57,26.67 95.89,26.35 96.2,26.35 96.52,26.04 97.47,26.04 97.77,25.38
  Route2 0.203: v77.47,60.01 77.15,59.69 77.15,46.99 77.47,46.67 77.79,46.67 77.79,46.35 78.11,46.04 78.11,40.32 78.42,40.01 78.42,39.69 78.74,39.37 78.74,29.53 v79.06,29.21
D3-1  (via drill 0.41 pad 0.61)
  Top 0.203: v47.62,59.05 49.53,59.05 49.85,59.37 50.8,59.37 51.12,59.69 52.07,59.69 52.07,59.37 52.39,59.05 53.66,59.05 53.98,58.42 | v47.94,23.5 77.79,23.5 78.11,23.81 78.11,26.04 87.95,26.04 88.27,25.72 88.58,25.72 88.9,25.4 89.22,25.4 89.53,25.08 89.53,24.13 95.57,24.13 95.89,23.81 96.2,23.81 96.52,23.5 97.47,23.5 97.77,22.84
  Bottom 0.203: v47.62,59.05 47.62,23.81 v47.94,23.5
D4-1  (via drill 0.41 pad 0.61)
  Top 0.203: v83.19,56.2 82.87,56.52 82.87,56.83 82.55,56.83 82.23,57.15 55.88,57.15 55.88,56.83 55.56,56.52 54.29,56.52 53.98,55.88
  Route2 0.203: v83.19,56.2 83.5,56.52 83.5,56.83 83.82,56.83 84.14,57.15 85.72,57.15 85.72,56.83 86.04,56.52 92.39,56.52 92.39,51.44 92.71,51.12 92.71,21.91 93.03,21.59 95.89,21.59 95.89,21.27 96.2,20.96 97.16,20.96 97.16,20.64 97.77,20.3
D5-1  (via drill 0.41 pad 0.61)
  Top 0.203: v80.01,52.07 78.74,52.07 78.74,52.39 78.42,52.7 56.83,52.7 56.52,53.34 | v85.09,20.96 87.95,20.96 88.27,20.64 89.22,20.64 89.53,20.32 93.03,20.32 93.34,20 93.34,19.05 95.57,19.05 95.89,18.73 96.2,18.73 96.52,18.41 97.47,18.41 97.77,17.76
  Bottom 0.203: v80.01,52.07 80.33,51.75 80.33,51.44 80.64,51.12 80.64,47.94 80.96,47.62 80.96,47.31 81.28,47.31 81.6,46.99 82.55,46.99 82.55,46.67 82.87,46.35 83.19,46.35 83.19,45.4 83.5,45.09 83.5,44.77 83.82,44.77 84.14,44.45 85.72,44.45 85.72,40.32 85.41,40.01 85.41,21.91 85.09,21.59 v85.09,20.96
D6-1  (via drill 0.41 pad 0.61)
  Route15 0.203: v52.39,19.05 52.7,19.37 59.37,19.37 59.69,19.05 69.85,19.05 70.17,18.73 79.38,18.73 79.69,18.41 87.95,18.41 88.27,18.1 88.58,18.1 88.9,17.78 93.03,17.78 93.34,17.46 93.34,16.51 95.57,16.51 95.89,16.19 96.2,16.19 96.52,15.88 97.47,15.88 97.77,15.21
  Bottom 0.203: v52.39,19.05 52.39,33.97 52.7,34.29 52.7,46.35 53.02,46.35 53.34,46.67 53.34,47.94 53.98,48.26
D7-1  (via drill 0.41 pad 0.61)
  Top 0.203: v66.36,8.89 79.06,8.89 79.38,8.57 79.38,8.26 87.95,8.26 88.27,8.57 88.58,8.57 88.9,8.89 89.22,8.89 89.53,9.21 89.85,9.21 89.85,10.48 97.16,10.48 97.47,10.79 97.47,12.07 JP2.
  Route2 0.203: v66.36,8.89 66.36,9.53 53.02,9.53 52.7,9.84 52.7,13.34 54.29,13.34 54.61,13.65 54.61,39.37 54.93,39.69 54.93,40.01 55.24,40.32 55.24,43.81 55.56,43.81 55.88,44.13 55.88,45.4 56.52,45.72
DIN-1  (via drill 0.41 pad 0.61)
  Top 0.203: v55.24,76.2 v93.34,76.2
  Bottom 0.203: v55.24,76.2 55.24,73.03 54.93,73.03 54.61,72.71 54.61,71.44 53.98,71.12 | v93.34,76.2 93.34,44.77 93.66,44.45 93.98,44.45 93.98,42.86 94.3,42.55 94.3,41.27 94.61,40.96 95.22,40.62 95.89,40.32 95.89,39.37 96.2,39.05 96.2,38.73 96.52,38.42 96.52,32.7 96.84,32.39 96.84,32.07 97.16,31.75 97.16,30.8 97.77,30.46
DM0-1  (via drill 0.41 pad 0.61)
  Top 0.203: 12.7,8.26 15.24,8.26 15.24,8.89 29.84,8.89 30.16,9.21 30.16,9.53 32.38,9.53 v39.37,9.53 | 47.62,9.53 50.16,9.53 50.16,8.89 v56.2,8.89 60.64,8.89 61.28,8.26 62.87,8.26 | v66.36,17.46 71.75,17.46 72.07,17.78 78.11,17.78 78.42,18.1 79.38,18.1 79.69,18.41 80.64,18.41 80.64,18.1 80.96,17.78 87.31,17.78 87.63,17.14
  Route15 0.203: v39.37,9.53 39.37,8.89 v56.2,8.89
  Bottom 0.203: 57.47,11.75 57.47,9.21 57.15,8.89 v56.2,8.89 | 57.47,11.75 57.47,39.69 57.15,40.01 57.15,40.32 56.52,40.64 | v66.36,17.46 66.67,17.14 66.67,13.65 66.36,13.34 65.09,13.34 65.09,12.07 64.77,11.75 57.47,11.75
DM1-1  (via drill 0.41 pad 0.61)
  Top 0.203: v33.97,7.94 33.66,8.26 | 15.88,5.08 v15.88,7.62 | 33.66,8.26 32.38,8.26 | 33.66,8.26 35.88,8.26 35.88,7.94 36.2,7.62 43.81,7.62 43.81,7.94 44.13,7.94 44.45,8.26 47.62,8.26 v49.21,8.26 | v60.33,6.35 65.09,6.35 65.41,5.71 | v64.77,10.16 78.11,10.16 78.42,10.48 79.38,10.48 79.69,10.79 89.53,10.79 89.53,13.65 89.22,13.97 87.95,13.97 87.63,14.61
  Route15 0.203: v15.88,7.62 16.19,7.94 v33.97,7.94
  Bottom 0.203: 54.61,6.35 v60.33,6.35 60.33,10.16 v64.77,10.16 | 54.61,6.35 54.61,40.32 53.98,40.64 | v49.21,8.26 50.16,8.26 50.16,5.4 50.48,5.08 54.61,5.08 54.61,6.35
DM2-1  (via drill 0.41 pad 0.61)
  Top 0.203: 17.14,5.08 17.14,7.62 31.11,7.62 31.43,7.3 32.38,6.99 40.01,6.99 40.01,6.67 40.32,6.35 v40.64,6.35 45.09,6.35 45.09,6.99 47.62,6.99 51.12,6.99 51.12,6.67 51.44,6.35 59.69,6.35 59.69,6.67 60.01,6.99 v64.45,6.99 66.04,6.99 66.36,6.67 66.67,5.71 | v43.81,42.55 49.21,42.55 49.21,43.5 49.53,43.5 49.85,43.81 50.16,43.81 50.48,44.13 50.8,44.13 51.12,44.45 52.07,44.45 52.07,44.77 52.39,45.09 53.66,45.09 53.98,45.72 | v65.72,12.7 78.74,12.7 79.06,13.02 79.38,13.02 79.69,13.34 80.64,13.34 80.64,13.02 80.96,12.7 87.31,12.7 87.63,12.07
  Bottom 0.203: v43.81,42.55 43.81,35.88 43.5,35.56 40.32,35.56 40.32,12.07 40.64,11.75 v40.64,6.35 | v65.72,12.7 65.72,7.3 65.41,6.99 v64.45,6.99
DM3-1  (via drill 0.41 pad 0.61)
  Top 0.203: 20.95,5.08 v20.95,6.67 | v34.61,5.71 42.55,5.71 43.5,5.4 45.4,5.4 45.72,5.08 50.48,5.08 50.8,5.4 v50.8,5.71 57.78,5.71 61.28,5.71 61.28,4.76 61.59,4.45 69.85,4.45 70.17,4.76 70.48,5.71
  Route15 0.203: v20.95,6.67 20.95,5.71 v34.61,5.71 | v50.8,5.71 70.17,5.71 70.17,9.84 70.48,10.16 78.74,10.16 79.06,10.48 79.38,10.48 79.69,10.79 80.33,10.79 80.64,10.48 85.09,10.48 85.41,10.16 87.31,10.16 87.63,9.53
  Bottom 0.203: v50.8,5.71 50.8,19.69 50.48,20 50.48,40.01 50.16,40.32 50.16,45.4 50.8,45.4 51.44,45.72
DM4-1  (via drill 0.41 pad 0.61)
  Top 0.203: v30.8,6.99 22.23,6.99 22.23,5.08 | 42.55,6.99 v44.13,6.99 44.45,6.99 44.45,7.3 44.77,7.62 55.24,7.62 55.24,6.99 57.78,6.99 | v71.75,4.13 71.75,5.71
  Route15 0.203: v30.8,6.99 v44.13,6.99 45.4,6.99 45.4,4.76 45.72,4.76 46.04,4.45 71.44,4.45 v71.75,4.13 | v44.77,43.18 45.09,43.5 46.35,43.5 46.35,45.09 46.67,45.4 47.62,45.4 47.62,48.58 47.94,48.9 50.16,48.9 50.48,49.21 50.8,49.21 51.12,49.53 54.61,49.53 54.61,49.85 54.93,50.16 56.2,50.16 56.52,50.8
  Bottom 0.203: v44.77,43.18 44.45,42.86 44.45,35.88 44.77,35.56 45.09,35.56 45.09,24.13 44.77,23.81 44.77,23.5 44.13,23.5 v44.13,6.99
DM5-1  (via drill 0.41 pad 0.61)
  Top 0.203: v39.37,6.35 23.5,6.35 23.5,5.08 | v40.01,8.26 42.55,8.26 43.5,8.57 44.13,8.57 44.45,8.89 49.53,8.89 49.85,8.57 49.85,8.26 v55.24,8.26 57.78,8.26 60.64,8.26 60.64,7.94 60.96,7.62 73.03,7.62 73.03,5.71
  Bottom 0.203: v39.37,6.35 40.01,6.35 v40.01,8.26 | v55.24,8.26 55.24,48.9 54.93,48.9 54.61,49.21 54.61,50.48 53.98,50.8
DM6-1  (via drill 0.41 pad 0.61)
  Top 0.203: U4. 30.16,8.26 30.48,8.57 30.48,8.89 39.69,8.89 40.01,9.21 40.01,9.53 42.55,9.53 45.72,9.53 45.72,9.84 46.04,10.16 | 46.04,10.16 55.24,10.16 55.24,9.53 57.78,9.53 60.96,9.53 60.96,9.21 61.28,8.89 64.77,8.89 64.77,8.57 65.09,8.26 75.56,8.26 | 46.04,10.16 v45.4,10.16 | v46.35,50.8 51.44,50.8
  Bottom 0.203: v46.35,50.8 46.35,45.4 46.04,45.09 45.72,45.09 45.72,24.13 45.4,23.81 v45.4,10.16
DM7-1  (via drill 0.41 pad 0.61)
  Top 0.203: 26.67,9.53 29.53,9.53 29.84,9.84 29.84,10.16 38.73,10.16 39.05,10.48 39.05,10.79 42.55,10.79 45.4,10.79 45.4,11.11 45.72,11.43 v49.53,11.43 49.53,11.11 49.85,10.79 57.78,10.79 60.96,10.79 60.96,10.48 61.28,10.16 64.14,10.16 64.14,9.84 64.45,9.53 75.56,9.53
  Bottom 0.203: v49.53,11.43 49.53,49.53 51.75,49.53 52.07,49.85 52.39,49.85 52.39,50.16 52.7,50.48 52.7,56.52 52.39,56.52 52.07,56.83 52.07,58.1 51.44,58.42
DP0-1  (via drill 0.41 pad 0.61)
  Top 0.203: v75.56,74.93 75.56,75.56 91.76,75.56 92.08,75.25 92.08,73.66 94.61,73.66 95.22,73.63
  Bottom 0.203: v75.56,74.93 75.56,67.94 75.25,67.94 74.93,67.63 74.93,46.04 74.3,45.72
DP1-1  (via drill 0.41 pad 0.61)
  Top 0.203: v86.36,71.12 94.61,71.12 95.22,71.09
  Bottom 0.203: v86.36,71.12 86.36,67.31 79.06,67.31 78.74,66.99 78.42,66.99 78.42,66.67 78.11,66.36 78.11,57.15 79.69,57.15 80.01,56.83 80.33,56.83 80.33,56.52 80.64,56.2 80.64,55.24 80.33,55.24 80.01,54.93 80.01,54.61 79.06,54.61 78.74,54.29 78.42,54.29 78.42,53.98 78.11,53.66 78.11,45.09 77.79,45.09 77.47,44.77 77.47,43.5 76.83,43.18
DP2-1  (via drill 0.41 pad 0.61)
  Route15 0.203: v72.39,65.41 72.39,66.67 78.42,66.67 78.74,66.99 78.74,67.31 84.77,67.31 85.09,67.63 85.41,67.63 85.72,67.94 94.93,67.94 95.22,68.56
  Bottom 0.203: v72.39,65.41 72.39,46.04 71.75,45.72
DP3-1  (via drill 0.41 pad 0.61)
  Top 0.203: v87.63,66.04 94.61,66.04 95.22,66.02
  Route15 0.203: v87.63,52.07 87,52.07 87,47.31 86.68,46.99 86.68,42.86 86.36,42.86 86.04,42.55 85.72,42.55 85.41,42.23 85.09,42.23 84.77,41.91 76.2,41.91 76.2,41.59 75.88,41.27 74.61,41.27 74.3,40.64
  Bottom 0.203: v87.63,52.07 v87.63,66.04
DP4-1  (via drill 0.41 pad 0.61)
  Top 0.203: v93.34,40.01 93.34,40.64 93.03,40.96 86.36,40.96 86.04,41.27 85.72,41.27 85.41,41.59 85.09,41.59 84.77,41.91 73.66,41.91 73.66,42.23 73.34,42.55 72.07,42.55 71.75,43.18 | v92.71,63.5 94.61,63.5 95.22,63.48
  Bottom 0.203: v93.34,40.01 93.03,40.32 93.03,40.64 92.71,40.96 v92.71,63.5
DP5-1  (via drill 0.41 pad 0.61)
  Top 0.203: v91.44,40.01 89.22,40.01 88.9,39.69 85.09,39.69 84.77,39.37 72.07,39.37 72.07,40.01 71.75,40.64 | v91.44,60.33 94.93,60.33 95.22,60.94
  Bottom 0.203: v91.44,40.01 v91.44,60.33
DP6-1  (via drill 0.41 pad 0.61)
  Top 0.203: v87,38.73 70.48,38.73 70.48,40.96 70.17,41.27 70.17,41.59 69.85,41.59 69.53,41.91 69.53,42.55 69.22,43.18 | v87,57.79 94.93,57.79 95.22,58.4
  Bottom 0.203: v87,38.73 v87,57.79
DP7-1
  Route15 0.203: 66.67,40.64 66.99,40.01 68.26,40.01 68.58,39.69 68.58,38.42 86.04,38.42 86.36,38.73 86.36,42.23 88.27,42.23 88.58,42.55 88.9,42.55 88.9,53.98 91.76,53.98 92.08,54.29 92.08,55.88 94.61,55.88 95.22,55.85
EP0-1
  Route15 0.203: 13.97,54.61 13.65,53.98 11.75,53.98 11.43,53.66 11.43,39.37 26.99,39.37 27.3,39.69 27.3,40.01 49.21,40.01 49.53,40.32 49.53,46.99 58.42,46.99 58.74,47.31 58.74,49.53 79.69,49.53 80.01,49.85 80.33,49.85 80.64,50.16 81.6,50.16 81.92,50.8
EP1-1  (via drill 0.41 pad 0.61)
  Top 0.203: v17.46,50.48 41.27,50.48 41.59,50.8 44.77,50.8 45.09,51.12 45.4,51.12 45.72,51.44 50.48,51.44 50.8,51.75 50.8,52.07 76.83,52.07 77.15,51.75 77.15,50.8 79.38,50.8
  Bottom 0.203: v17.46,50.48 17.46,50.8 16.19,50.8 15.88,51.12 15.56,51.12 15.56,51.44 15.24,51.75 14.61,51.75 13.97,52.07
GND  (via drill 0.41 pad 0.61)
  Top 0.203: 44.45,52.07 44.77,52.7 49.21,52.7 49.53,53.02 49.53,57.15 54.29,57.15 54.61,57.47 54.93,57.47 55.24,57.79 56.2,57.79 56.52,58.42 79.38,58.42 | 66.99,66.67 66.99,67.94 66.67,68.58 | 66.99,66.67 66.99,66.36 67.31,66.04 79.38,66.04 | 66.99,47.62 66.99,48.26 79.38,48.26 | 66.99,47.62 66.99,46.35 66.67,45.72 | 66.99,47.62 59.69,47.62 59.37,47.31 59.37,46.35 59.05,45.72 | 66.99,66.67 59.69,66.67 59.37,66.99 59.37,67.94 59.05,68.58 | 64.14,26.04 60.64,26.04 60.64,26.35 60.33,26.67 53.98,26.67 53.98,26.04 51.44,26.04 50.48,25.72 50.48,24.77 42.86,24.77 42.55,25.08 36.2,25.08 35.88,25.4 35.56,26.04 34.92,25.72 33.34,25.72 32.38,25.78 31.43,25.72 28.89,25.72 28.57,26.04 28.26,26.04 27.94,26.67 | v38.73,36.51 33.34,36.51 32.38,36.45 | 71.12,3.81 71.12,6.99 68.58,6.99 68.26,6.67 67.94,5.71 | 65.09,3.81 71.12,3.81 | 65.09,3.81 65.09,3.49 65.15,2.54 | 80.33,4.45 88.58,4.45 88.9,3.81 | 80.33,4.45 80.33,3.49 80.39,2.54 80.01,3.49 71.44,3.49 71.12,3.81 | 80.33,4.45 80.33,6.35 80.01,6.99 | 47.94,4.13 v45.4,4.13 37.47,4.13 37.15,4.45 32.7,4.45 | 47.94,4.13 47.94,3.49 48.01,2.54 | v46.04,5.71 47.62,5.71 | 18.41,3.81 18.41,3.49 18.16,2.54 17.78,3.18 14.61,3.18 14.61,5.4 14.29,5.71 2.86,5.71 2.86,10.48 2.41,11.05 | 18.41,3.81 18.41,5.08 | 32.7,3.81 32.7,3.49 32.77,2.54 | 32.7,3.81 32.7,4.45 | 32.7,4.45 32.7,5.4 32.38,5.71 | 18.41,3.81 32.7,3.81 | 65.09,3.81 53.02,3.81 52.7,4.13 52.7,4.45 47.94,4.45 47.94,4.13
  Bottom 0.203: 59.05,68.58 59.05,45.72 | 79.38,58.42 80.01,58.74 80.01,60.01 80.33,60.33 80.64,60.33 80.64,63.82 80.33,64.13 80.33,64.45 80.01,64.77 80.01,65.72 79.38,66.04 | 21.59,41.91 22.23,41.59 22.23,30.16 22.54,29.84 27.94,29.84 27.94,26.67 | 38.73,22.54 v38.73,36.51 38.73,41.59 39.37,41.91 40.01,42.23 40.01,43.18 42.23,43.18 42.55,43.5 42.86,43.5 42.86,43.81 43.18,44.13 43.18,50.16 43.5,50.16 43.81,50.48 43.81,51.75 44.45,52.07 | 38.73,22.54 38.42,22.23 35.56,22.23 35.56,26.04 | 95.22,12.68 94.61,12.38 93.34,12.38 93.34,2.22 93.03,1.91 88.9,1.91 88.9,3.81 | 3.17,18.73 3.17,17.14 3.49,16.83 3.49,12.7 3.17,12.38 3.17,11.11 2.41,11.05 | 3.17,18.73 3.17,20 3.49,20.32 3.49,29.53 3.17,29.84 3.17,31.43 2.41,31.37 | 3.17,18.73 2.41,18.67 | 45.4,5.71 v46.04,5.71 | v45.4,4.13 45.4,5.71 | 38.73,22.54 38.73,6.03 39.05,5.71 45.4,5.71
HDC-1  (via drill 0.41 pad 0.61)
  Top 0.203: v81.92,35.88 82.23,35.56 83.19,35.56 83.19,34.61 84.14,34.61 R12.
  Bottom 0.203: v81.92,35.88 81.92,40.64
LDC-1  (via drill 0.41 pad 0.61)
  Top 0.203: 60.33,34.04 61.28,33.97 61.91,33.97 61.91,32.39 64.14,32.39 66.67,32.39 v66.99,32.7
  Route15 0.203: v66.99,32.7 v76.2,32.7
  Bottom 0.203: v76.2,32.7 76.2,40.32 76.83,40.64
N00044  (via drill 0.41 pad 0.61)
  Top 0.203: v78.11,36.83 78.11,36.2 73.98,36.2 73.66,35.88 73.66,34.61 73.34,34.61 72.39,34.54
  Bottom 0.203: v78.11,36.83 78.11,41.27 78.42,41.27 78.74,41.59 78.74,42.86 79.38,43.18
N00107
  Top 0.203: D2. 10.48,78.74 16.83,78.74 17.14,79.06 17.14,80.65 20.32,80.65 D3.
N00117
  Top 0.203: 35.56,28.57 34.92,28.89 33.34,28.89 C5.
N00118
  Top 0.203: 35.56,33.66 34.92,33.34 33.34,33.34 C4.
N00119  (via drill 0.41 pad 0.61)
  Top 0.203: v66.04,30.48 60.96,30.48 60.64,30.16 60.64,29.84 57.15,29.84 | v68.9,10.79 75.56,10.79
  Route2 0.203: v68.9,10.79 68.58,11.11 68.58,30.16 68.26,30.48 v66.04,30.48
N00121  (via drill 0.41 pad 0.61)
  Top 0.203: v72.07,24.13 58.1,24.13 58.1,25.72 U3. | v72.07,19.37 71.75,19.69 71.75,20.96
  Bottom 0.203: v72.07,24.13 v72.07,19.37
N00124  (via drill 0.41 pad 0.61)
  Top 0.203: v60.01,27.94 53.98,27.94 53.98,27.3 51.44,27.3 | v60.01,19.69 67.94,19.69 67.94,20.96
  Bottom 0.203: v60.01,27.94 v60.01,19.69
N00135
  Top 0.203: 51.44,31.12 48.58,31.12 48.26,31.43 48.26,33.02 58.42,33.02 58.42,35.24 62.23,35.24 62.55,34.92 62.55,33.66 64.14,33.66
N00157  (via drill 0.41 pad 0.61)
  Top 0.203: v91.44,31.43 86.04,31.43 85.09,31.5
  Bottom 0.203: D5. v91.44,31.43
P00-1  (via drill 0.41 pad 0.61)
  Top 0.203: v39.05,68.58 39.69,68.58 40.01,68.9 40.32,68.9 40.32,69.22 40.64,69.53 40.64,70.49 40.96,70.49 41.27,70.8 41.27,71.12 44.77,71.12 45.09,70.8 47.94,70.8 48.26,70.49 48.58,70.49 48.58,69.85 54.29,69.85 54.61,70.17 54.93,70.17 55.24,70.49 56.2,70.49 56.52,71.12
  Bottom 0.203: v39.05,68.58 38.73,68.26 38.73,44.77 39.37,44.45
P01-1  (via drill 0.41 pad 0.61)
  Route2 0.203: v47.62,80.65 47.62,66.04 47.31,66.04 46.99,65.72 46.99,42.55 45.09,42.55 44.77,42.23 44.77,41.91 41.91,41.91
  Bottom 0.203: v47.62,80.65 53.98,80.65 53.98,73.66
P02-1  (via drill 0.41 pad 0.61)
  Top 0.203: v58.1,47.62 57.78,47.62 57.47,47.31 57.15,47.31 56.83,46.99 49.53,46.99 49.53,45.4 49.21,45.09 44.77,45.09 44.45,44.45
  Bottom 0.203: v58.1,47.62 58.42,47.94 58.42,67.63 58.1,67.94 57.78,67.94 57.78,68.9 58.1,69.22 58.1,69.53 58.42,69.85 58.42,70.8 59.05,71.12
P03-1  (via drill 0.41 pad 0.61)
  Top 0.203: v40.64,76.84 v59.05,76.84
  Bottom 0.203: v40.64,76.84 40.64,69.53 40.32,69.22 40.32,68.9 40.01,68.9 39.69,68.58 39.69,68.26 39.37,67.94 39.37,46.35 40.96,46.35 41.27,46.04 41.27,44.77 41.91,44.45 | v59.05,76.84 59.05,73.66
P04-1  (via drill 0.41 pad 0.61)
  Top 0.203: v46.35,72.39 61.91,72.39 62.23,72.07 62.55,72.07 62.87,71.75 63.82,71.75 64.14,71.12
  Bottom 0.203: v46.35,72.39 46.35,51.44 46.04,51.44 45.72,51.12 45.72,47.31 45.09,47.31 44.45,46.99
P05-1  (via drill 0.41 pad 0.61)
  Top 0.203: v65.41,50.16 58.42,50.16 58.1,49.85 57.15,49.85 56.83,49.53 50.8,49.53 50.8,49.21 50.48,48.9 46.35,48.9 46.04,48.58 45.09,48.58 44.77,48.26 43.81,48.26 43.81,47.94 43.5,47.62 42.23,47.62 41.91,46.99
  Bottom 0.203: v65.41,50.16 65.41,68.9 65.72,69.22 65.72,69.53 66.04,69.85 66.04,70.8 66.67,71.12
P06-1  (via drill 0.41 pad 0.61)
  Top 0.203: v45.72,74.93 66.99,74.93 67.31,74.61 68.58,74.61 68.9,74.29 69.22,73.66
  Bottom 0.203: v45.72,74.93 45.72,51.75 45.09,51.12 45.09,49.85 44.45,49.53
P07-1  (via drill 0.41 pad 0.61)
  Route15 0.203: v70.48,55.24 57.78,55.24 57.47,54.93 57.15,54.93 56.83,54.61 46.99,54.61 46.99,51.75 46.67,51.44 45.72,51.44 45.4,51.12 45.09,51.12 44.77,50.8 43.81,50.8 43.81,50.48 43.5,50.16 42.23,50.16 41.91,49.53
  Bottom 0.203: v70.48,55.24 70.48,71.44 70.8,71.75 70.8,72.07 71.12,72.07 71.44,72.39 73.66,72.39 73.66,73.34 74.3,73.66
P10-1
  Top 0.203: 2.41,41.53 2.54,42.23 3.81,42.23 4.13,42.55 4.45,42.55 4.76,42.86 12.06,42.86 12.38,42.55 15.56,42.55 15.88,42.86 15.88,43.18 16.83,43.18 17.14,43.5 17.46,43.5 17.78,43.81 18.73,43.81 19.05,44.45
P11-1
  Top 0.203: 2.41,38.99 2.54,39.69 3.81,39.69 4.13,40.01 4.45,40.01 4.76,40.32 18.1,40.32 18.41,40.64 18.73,40.64 18.73,41.27 19.05,41.91
P12-1  (via drill 0.41 pad 0.61)
  Top 0.203: v6.67,43.5 13.34,43.5 13.65,43.18 14.29,43.18 14.61,43.5 15.56,43.5 15.88,43.81 16.19,43.81 16.51,44.45
  Bottom 0.203: v6.67,43.5 6.67,37.78 4.76,37.78 4.45,37.47 4.13,37.47 3.81,37.15 3.81,36.51 3.17,36.51 2.41,36.45
P13-1  (via drill 0.41 pad 0.61)
  Top 0.203: v16.51,36.2 11.11,36.2 10.79,35.88 6.67,35.88 6.35,35.56 5.71,35.56 5.4,35.24 4.76,35.24 4.45,34.92 4.13,34.92 3.81,34.61 2.54,34.61 2.41,33.91
  Bottom 0.203: v16.51,36.2 16.51,41.91
P14-1  (via drill 0.41 pad 0.61)
  Route15 0.203: v14.61,15.24 79.06,15.24 79.38,15.56 79.38,15.88 87.95,15.88 88.27,15.56 88.58,15.56 88.9,15.24 94.61,15.24 95.22,15.21
  Bottom 0.203: v14.61,15.24 14.61,34.92 14.29,34.92 13.97,35.24 13.97,44.45
P15-1  (via drill 0.41 pad 0.61)
  Top 0.203: v14.61,35.56 11.75,35.56 11.75,34.92 11.43,34.61 5.08,34.61 4.95,33.91
  Bottom 0.203: v14.61,35.56 14.61,43.5 14.92,43.81 15.24,43.81 15.24,44.77 15.56,45.09 15.56,45.4 15.88,45.72 15.88,46.67 16.51,46.99
P16-1  (via drill 0.41 pad 0.61)
  Top 0.203: v7.3,46.99 13.97,46.99
  Bottom 0.203: v7.3,46.99 7.3,31.43 5.71,31.43 4.95,31.37
P20-1  (via drill 0.41 pad 0.61)
  Top 0.203: 57.78,18.41 50.16,18.41 49.53,19.05 45.4,19.05 45.09,18.73 45.09,18.41 42.55,18.41 35.56,18.41 35.56,18.73 35.24,19.05 29.84,19.05 29.53,18.73 27.62,18.73 26.67,18.41 v24.13,18.41 | v25.4,76.84 39.69,76.84 39.69,75.88 40.01,75.56 74.93,75.56 74.93,74.61 75.25,74.29 75.56,74.29 75.56,73.34 75.88,73.03 75.88,72.71 76.2,72.71 76.52,72.39 76.52,71.75 76.83,71.12
  Route2 0.203: v24.13,18.41 24.13,30.8 24.45,31.12 24.45,39.69 25.72,39.69 26.04,40.01 26.04,41.59 26.67,41.91
  Bottom 0.203: v25.4,76.84 25.4,44.13 25.72,43.81 25.72,43.5 26.04,43.18 26.04,42.23 26.67,41.91
P21-1  (via drill 0.41 pad 0.61)
  Top 0.203: 26.67,17.14 29.53,17.14 30.16,17.78 v30.48,17.78 34.29,17.78 34.92,17.14 42.55,17.14 45.09,17.14 45.72,17.78 49.53,17.78 50.16,17.14 57.78,17.14
  Route15 0.203: v27.62,71.44 27.94,71.75 27.94,73.98 28.26,74.29 29.84,74.29 29.84,75.25 30.16,75.56 82.23,75.56 82.23,74.93 82.87,74.29 83.19,74.29 83.19,73.34 82.87,73.03 82.87,72.71 82.55,72.71 82.23,72.39 81.28,72.39 81.28,72.07 80.96,71.75 79.69,71.75 79.38,71.12
  Bottom 0.203: v30.48,17.78 30.16,17.78 29.84,18.1 29.84,39.69 28.89,39.69 28.89,40.01 28.57,40.32 28.57,40.64 28.26,40.96 28.26,41.27 27.94,41.59 27.94,42.55 27.62,42.55 27.3,42.86 27.3,44.13 26.67,44.45 27.3,44.77 27.3,67.94 27.62,68.26 27.62,69.22 27.94,69.53 27.94,71.12 v27.62,71.44
P22-1  (via drill 0.41 pad 0.61)
  Top 0.203: 57.78,13.34 54.29,13.34 54.29,13.65 53.98,13.97 44.45,13.97 43.81,13.34 42.55,13.34 40.32,13.34 39.69,13.97 v38.1,13.97 | v30.8,12.7 28.89,12.7 28.26,12.07 26.67,12.07 | v81.92,80.65 49.21,80.65 48.9,80.33 48.9,80.01 33.34,80.01 33.02,79.69 33.02,79.38 32.07,79.38 31.75,79.06 30.8,79.06 30.48,78.74 v30.16,78.74
  Route2 0.203: v30.8,12.7 31.43,12.7 31.43,22.86 31.11,23.18 31.11,23.5 30.48,23.5 30.48,38.42 30.16,38.73 29.21,38.73 29.21,41.91 29.84,42.23 29.84,43.18 30.16,43.5 30.16,43.81 30.48,44.13 30.48,72.71 30.16,73.03 v30.16,78.74
  Route15 0.203: v38.1,13.97 38.1,14.61 30.16,14.61 29.84,14.29 29.84,12.7 v30.8,12.7
  Bottom 0.203: v81.92,80.65 81.92,73.66
P23-1  (via drill 0.41 pad 0.61)
  Top 0.203: 26.67,15.88 29.53,15.88 30.16,16.51 v30.48,16.51 34.29,16.51 34.92,15.88 42.55,15.88 45.09,15.88 45.72,16.51 49.53,16.51 50.16,15.88 57.78,15.88 | v34.29,79.38 v76.83,79.38
  Route2 0.203: v30.48,16.51 30.16,16.51 29.84,16.83 29.84,36.2 28.89,36.2 28.57,36.51 28.57,40.64 28.26,40.96 28.26,41.27 27.94,41.59 27.94,42.55 28.26,42.55 28.57,42.86 28.57,44.13 29.21,44.45
  Bottom 0.203: v34.29,79.38 34.29,74.61 33.97,74.29 33.02,74.29 33.02,69.53 32.7,69.22 32.7,68.9 32.38,68.58 32.38,68.26 32.07,67.94 32.07,67.63 29.21,67.63 29.21,44.45 | v76.83,79.38 76.83,73.66
P24-1  (via drill 0.41 pad 0.61)
  Top 0.203: 47.62,20.96 44.45,20.96 43.81,21.59 39.37,21.59 39.05,21.27 39.05,20.96 32.38,20.96 28.26,20.96 28.26,20.64 27.94,20.32 20.32,20.32 20.32,22.86 17.78,22.86 17.46,22.54 17.14,21.59 17.14,23.5 20.32,23.5 20.64,23.81 21.27,23.81 21.59,23.5 v31.75,23.5
  Route15 0.203: v73.03,51.44 72.71,51.75 57.15,51.75 56.83,52.07 51.12,52.07 50.8,51.75 50.48,51.75 50.16,51.44 47.31,51.44 46.99,51.12 46.99,48.26 41.59,48.26 41.27,47.94 40.96,47.94 40.64,47.62 33.34,47.62 33.02,47.31 33.02,43.81 32.7,43.81 32.38,43.5 32.38,42.55 32.07,42.55 31.75,41.91
  Bottom 0.203: v31.75,23.5 31.75,41.91 | v73.03,51.44 73.03,69.22 72.71,69.22 72.39,69.53 72.39,70.8 71.75,71.12
P25-1  (via drill 0.41 pad 0.61)
  Top 0.203: v36.2,19.05 40.32,19.05 40.32,19.69 42.55,19.69 | v36.2,21.59 v30.48,21.59 23.5,21.59 | v50.16,19.37 50.48,19.69 57.78,19.69 59.37,19.69 59.37,19.37 59.69,19.05 64.77,19.05 64.77,18.73 65.09,18.41 71.12,18.41 v71.44,18.1
  Route15 0.203: v50.16,19.37 49.85,19.05 v36.2,19.05
  Bottom 0.203: v36.2,21.59 v36.2,19.05 | v30.48,21.59 30.48,42.55 30.8,42.55 31.11,42.86 31.11,44.13 31.75,44.45 | v71.44,18.1 71.44,38.73 71.12,39.05 71.12,39.37 70.8,39.69 70.8,40.01 70.48,40.32 70.48,41.27 70.17,41.27 69.85,41.59 69.85,41.91 68.9,41.91 68.58,42.23 68.26,42.23 68.26,42.55 67.94,42.86 67.94,69.22 68.26,69.22 68.58,69.53 68.58,70.8 69.22,71.12
P26-1  (via drill 0.41 pad 0.61)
